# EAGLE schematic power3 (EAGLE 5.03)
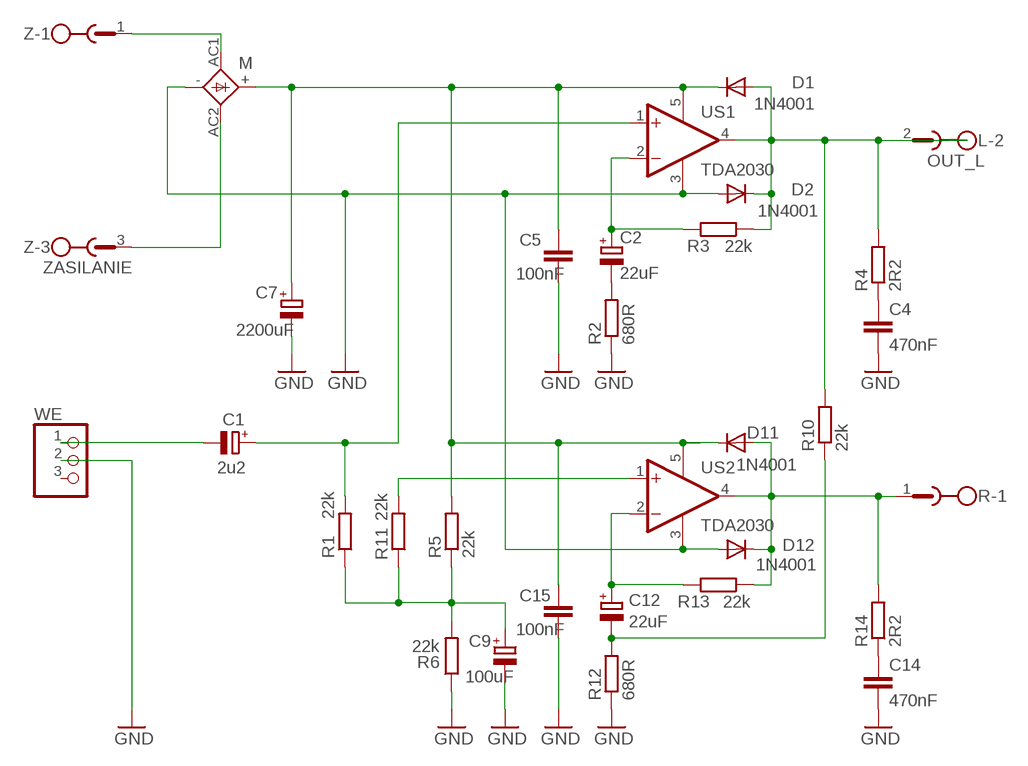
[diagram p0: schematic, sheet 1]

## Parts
C1  2u2  CPOL-EUE2.5-7  [E2,5-7]
C2  22uF  CPOL-EUE2.5-7  [E2,5-7]
C4  470nF  C-EU050-030X075  [C050-030X075]
C5  100nF  C-EU050-030X075  [C050-030X075]
C7  2200uF  CPOL-EUE7.5-16  [E7,5-16]
C9  100uF  CPOL-EUE2.5-7  [E2,5-7]
C12  22uF  CPOL-EUE2.5-7  [E2,5-7]
C14  470nF  C-EU050-030X075  [C050-030X075]
C15  100nF  C-EU050-030X075  [C050-030X075]
D1  1N4001  1N4148DO35-10  [DO35-10]
D2  1N4001  1N4148DO35-10  [DO35-10]
D11  1N4001  1N4148DO35-10  [DO35-10]
D12  1N4001  1N4148DO35-10  [DO35-10]
L  OUT_L  MSTBV2  [MSTBV2]
M  KBU  [KBU]
R  OUT_R  MSTBV2  [MSTBV2]
R1  22k  R-EU_0207/15  [0207/15]
R2  680R  R-EU_0207/10  [0207/10]
R3  22k  R-EU_0207/10  [0207/10]
R4  2R2  R-EU_0207/10  [0207/10]
R5  22k  R-EU_0207/10  [0207/10]
R6  22k  R-EU_0207/10  [0207/10]
R10  22k  R-EU_0207/12  [0207/12]
R11  22k  R-EU_0207/12  [0207/12]
R12  680R  R-EU_0207/15  [0207/15]
R13  22k  R-EU_0207/10  [0207/10]
R14  2R2  R-EU_0207/10  [0207/10]
US1  TDA2030  TDA2030V  [CB360]
US2  TDA2030  TDA2030V  [CB360]
WE  PINHD-1X3  [1X03]
Z  ZASILANIE  MSTBV3  [MSTBV3]

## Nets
GND: C4.2 C5.2 C7.- C9.- C14.2 C15.2 D2.A D12.A M.- R2.1 R6.1 R12.1 US1.3(GND) US2.3(GND) WE.2
N$1: C1.- WE.1
N$2: C1.+ R1.2 US1.1(+IN)
N$6: C9.+ R1.1 R5.1 R6.2 R11.1
N$7: M.AC1 Z.1
N$8: C2.+ R3.2 US1.2(-IN)
N$9: C12.- R10.1 R12.2
N$10: D1.A D2.C L.2 R3.1 R4.2 R10.2 US1.4(OUT)
N$11: R11.2 US2.1(+IN)
N$12: C4.1 R4.1
N$13: C2.- R2.2
N$14: M.AC2 Z.3
N$15: C5.1 C7.+ C15.1 D1.C D11.C M.+ R5.2 US1.5(V+) US2.5(V+)
N$16: C12.+ R13.2 US2.2(-IN)
N$17: D11.A D12.C R13.1 R14.2 R.1 US2.4(OUT)
N$18: C14.1 R14.1
Unconnected: L.1 R.2 WE.3 Z.2

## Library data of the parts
C1 C2 C7 C9 C12 = rcl:CPOL-EU: POLARIZED CAPACITOR, European symbol
C4 C5 C14 C15 = rcl:C-EU: CAPACITOR, European symbol
D1 D2 D11 D12 = diode:1N4148: DIODE
L R = con-phoenix-508:MSTBV2: PHOENIX
M = rectifier:KBU: DIOTEC RECTIFIER
R1-R6 R10-R14 = rcl:R-EU_: RESISTOR, European symbol
US1 US2 = linear:TDA2030: Power OP AMP
WE = pinhead:PINHD-1X3: PIN HEADER
Z = con-phoenix-508:MSTBV3: PHOENIX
